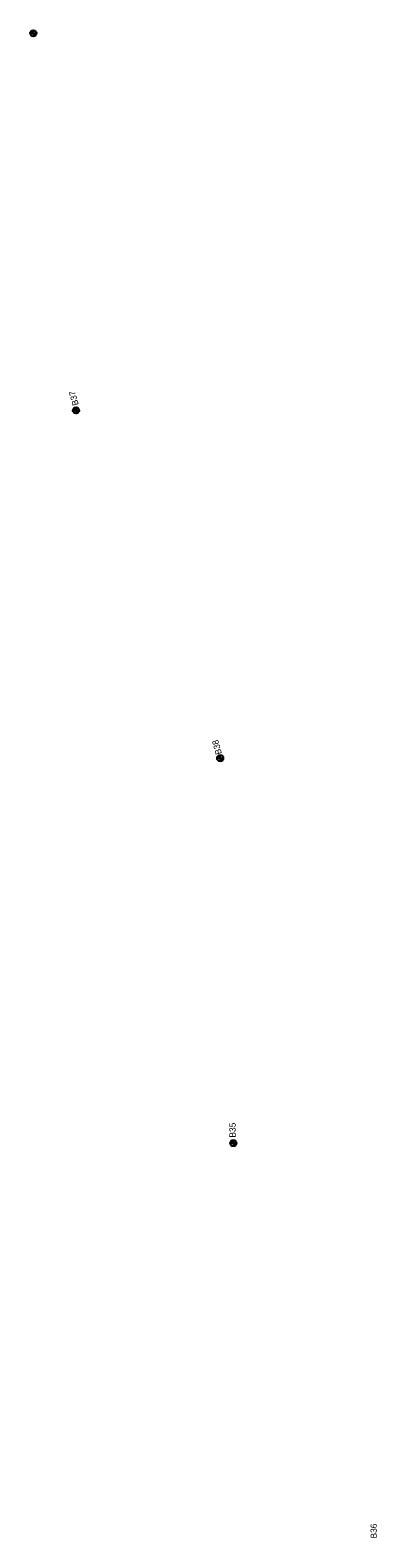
# Model space of a CAD drawing. Extents: x 327762 to 372792, y 127949 to 259367.
# Drawn here: x 360865 to 361420, y 147996 to 150410 of the extents above; entities that cross this region are included whole.
import ezdxf

# ---------------------------------------------------------------- set-up
doc = ezdxf.new("R2010")
doc.units = 0
for name, color, linetype in [('E_SOIL_BORE1 [KAPUR_CADDS_LEVELS]', 7, 'Continuous'), ('E_SOIL_BORE2 [KAPUR_CADDS_LEVELS]', 7, 'Continuous'), ('P_MARK', 7, 'Continuous')]:
    doc.layers.add(name, color=color, linetype=linetype)

msp = doc.modelspace()

# ---------------------------------------------------------------- linework, layer by layer
at = {"layer": 'P_MARK'}
for p, q in [((360870, 150410), (360870, 150400)), ((360865, 150405), (360875, 150405)), ((360938.5, 149806.2), (360938.5, 149796.2)), ((360933.5, 149801.2), (360943.5, 149801.2)), ((361169.4, 149249.4), (361169.4, 149239.4)), ((361164.4, 149244.4), (361174.4, 149244.4)), ((361185.6, 148628.1), (361195.6, 148628.1)), ((361190.6, 148633.1), (361190.6, 148623.1))]:
    msp.add_line(p, q, dxfattribs=at)
for centre in [(360870, 150405), (360938.5, 149801.2), (361169.4, 149244.4), (361190.6, 148628.1)]:
    msp.add_circle(centre, 5, dxfattribs=at)
for centre, radius, start, end in [((360870, 150405), 4.5, 89.9869, 179.9869), ((360870, 150405), 4, 89.9869, 179.9869), ((360870, 150405), 3.5, 89.9869, 179.9869), ((360870, 150405), 3, 89.9869, 179.9869), ((360870, 150405), 2.5, 89.9869, 179.9869), ((360870, 150405), 2, 89.9869, 179.9869), ((360870, 150405), 1.5, 89.9869, 179.9869), ((360870, 150405), 1, 89.9869, 179.9869), ((360870, 150405), 0.5, 89.9869, 179.9869), ((360870, 150405), 4.5, 269.9869, 359.9869), ((360870, 150405), 4, 269.9869, 359.9869), ((360870, 150405), 3.5, 269.9869, 359.9869), ((360870, 150405), 3, 269.9869, 359.9869), ((360870, 150405), 2.5, 269.9869, 359.9869), ((360870, 150405), 2, 269.9869, 359.9869), ((360870, 150405), 1.5, 269.9869, 359.9869), ((360870, 150405), 1, 269.9869, 359.9869), ((360870, 150405), 0.5, 269.9869, 359.9869), ((360938.5, 149801.2), 4.5, 89.9869, 179.9869), ((360938.5, 149801.2), 4, 89.9869, 179.9869), ((360938.5, 149801.2), 3.5, 89.9869, 179.9869), ((360938.5, 149801.2), 3, 89.9869, 179.9869), ((360938.5, 149801.2), 2.5, 89.9869, 179.9869), ((360938.5, 149801.2), 2, 89.9869, 179.9869), ((360938.5, 149801.2), 1.5, 89.9869, 179.9869), ((360938.5, 149801.2), 1, 89.9869, 179.9869), ((360938.5, 149801.2), 0.5, 89.9869, 179.9869), ((360938.5, 149801.2), 4.5, 269.9869, 359.9869), ((360938.5, 149801.2), 4, 269.9869, 359.9869), ((360938.5, 149801.2), 3.5, 269.9869, 359.9869), ((360938.5, 149801.2), 3, 269.9869, 359.9869), ((360938.5, 149801.2), 2.5, 269.9869, 359.9869), ((360938.5, 149801.2), 2, 269.9869, 359.9869), ((360938.5, 149801.2), 1.5, 269.9869, 359.9869), ((360938.5, 149801.2), 1, 269.9869, 359.9869), ((360938.5, 149801.2), 0.5, 269.9869, 359.9869), ((361169.4, 149244.4), 4.5, 89.9869, 179.9869), ((361169.4, 149244.4), 4, 89.9869, 179.9869), ((361169.4, 149244.4), 3.5, 89.9869, 179.9869), ((361169.4, 149244.4), 3, 89.9869, 179.9869), ((361169.4, 149244.4), 2.5, 89.9869, 179.9869), ((361169.4, 149244.4), 2, 89.9869, 179.9869), ((361169.4, 149244.4), 1.5, 89.9869, 179.9869), ((361169.4, 149244.4), 1, 89.9869, 179.9869), ((361169.4, 149244.4), 0.5, 89.9869, 179.9869), ((361169.4, 149244.4), 4.5, 269.9869, 359.9869), ((361169.4, 149244.4), 4, 269.9869, 359.9869), ((361169.4, 149244.4), 3.5, 269.9869, 359.9869), ((361169.4, 149244.4), 3, 269.9869, 359.9869), ((361169.4, 149244.4), 2.5, 269.9869, 359.9869), ((361169.4, 149244.4), 2, 269.9869, 359.9869), ((361169.4, 149244.4), 1.5, 269.9869, 359.9869), ((361169.4, 149244.4), 1, 269.9869, 359.9869), ((361169.4, 149244.4), 0.5, 269.9869, 359.9869), ((361190.6, 148628.1), 4.5, 89.9869, 179.9869), ((361190.6, 148628.1), 4, 89.9869, 179.9869), ((361190.6, 148628.1), 3.5, 89.9869, 179.9869), ((361190.6, 148628.1), 3, 89.9869, 179.9869), ((361190.6, 148628.1), 2.5, 89.9869, 179.9869), ((361190.6, 148628.1), 2, 89.9869, 179.9869), ((361190.6, 148628.1), 1.5, 89.9869, 179.9869), ((361190.6, 148628.1), 1, 89.9869, 179.9869), ((361190.6, 148628.1), 0.5, 89.9869, 179.9869), ((361190.6, 148628.1), 4.5, 269.9869, 359.9869), ((361190.6, 148628.1), 4, 269.9869, 359.9869), ((361190.6, 148628.1), 3.5, 269.9869, 359.9869), ((361190.6, 148628.1), 3, 269.9869, 359.9869), ((361190.6, 148628.1), 2.5, 269.9869, 359.9869), ((361190.6, 148628.1), 2, 269.9869, 359.9869), ((361190.6, 148628.1), 1.5, 269.9869, 359.9869), ((361190.6, 148628.1), 1, 269.9869, 359.9869), ((361190.6, 148628.1), 0.5, 269.9869, 359.9869)]:
    msp.add_arc(centre, radius, start, end, dxfattribs=at)

# ---------------------------------------------------------------- texts
at = {"layer": 'E_SOIL_BORE1 [KAPUR_CADDS_LEVELS]'}
msp.add_text('B37', height=10, rotation=105.7466, dxfattribs=at).set_placement((360942.9, 149810.5))
at = {"layer": 'E_SOIL_BORE2 [KAPUR_CADDS_LEVELS]'}
for s, rotation, p in [('B38', 105.7466, (361172.2, 149251.8)), ('B35', 89.9869, (361194.1, 148637)), ('B36', 89.9869, (361420.2, 147995.1))]:
    msp.add_text(s, height=10, rotation=rotation, dxfattribs=at).set_placement(p)

doc.saveas('drawing.dxf')
